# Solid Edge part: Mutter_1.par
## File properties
Dokumentum tartalom típus: 0
Last saved by: ahadarics
Revision: 77
Sűrűség: 0,000 kg/m^3
Pontosság: 0,990
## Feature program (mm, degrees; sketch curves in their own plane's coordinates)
base feature "unnamed BaseFeature 1"
thread "unnamed Thread 1"
chamfer "Letörés_1"  SetBackValue2 = 60 deg
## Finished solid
Body 1: solid body, 23 faces, 46 edges, 24 vertices.
  Faces by surface: cone 14, plane 8, cylinder 1
  Edges by curve: spline 24, circle 16, line 6
Bounding box of the edges (mm): 8.000 x 27.713 x 24.000, from (0, -13.8564, -12) to (8, 13.8564, 12).
Cylindrical faces by radius (mm): R7.188 x1
Conical faces (half-angle, radius in mm at the cone's reference point): 60 deg R7.188 x1, 60 deg R8.054 x1, 60 deg R12.9282 x12
Planar faces by outward normal: +x 1, +z 1, -x 1, -z 1, oblique 4
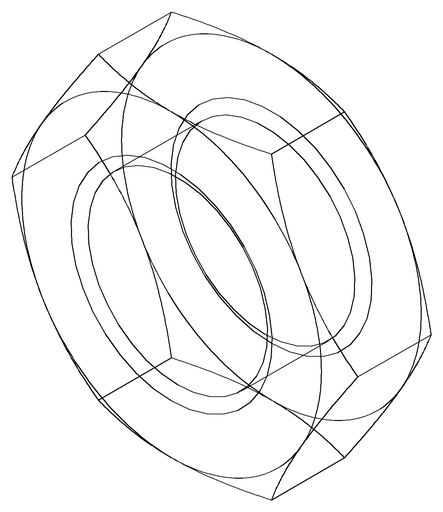
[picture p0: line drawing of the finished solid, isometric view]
